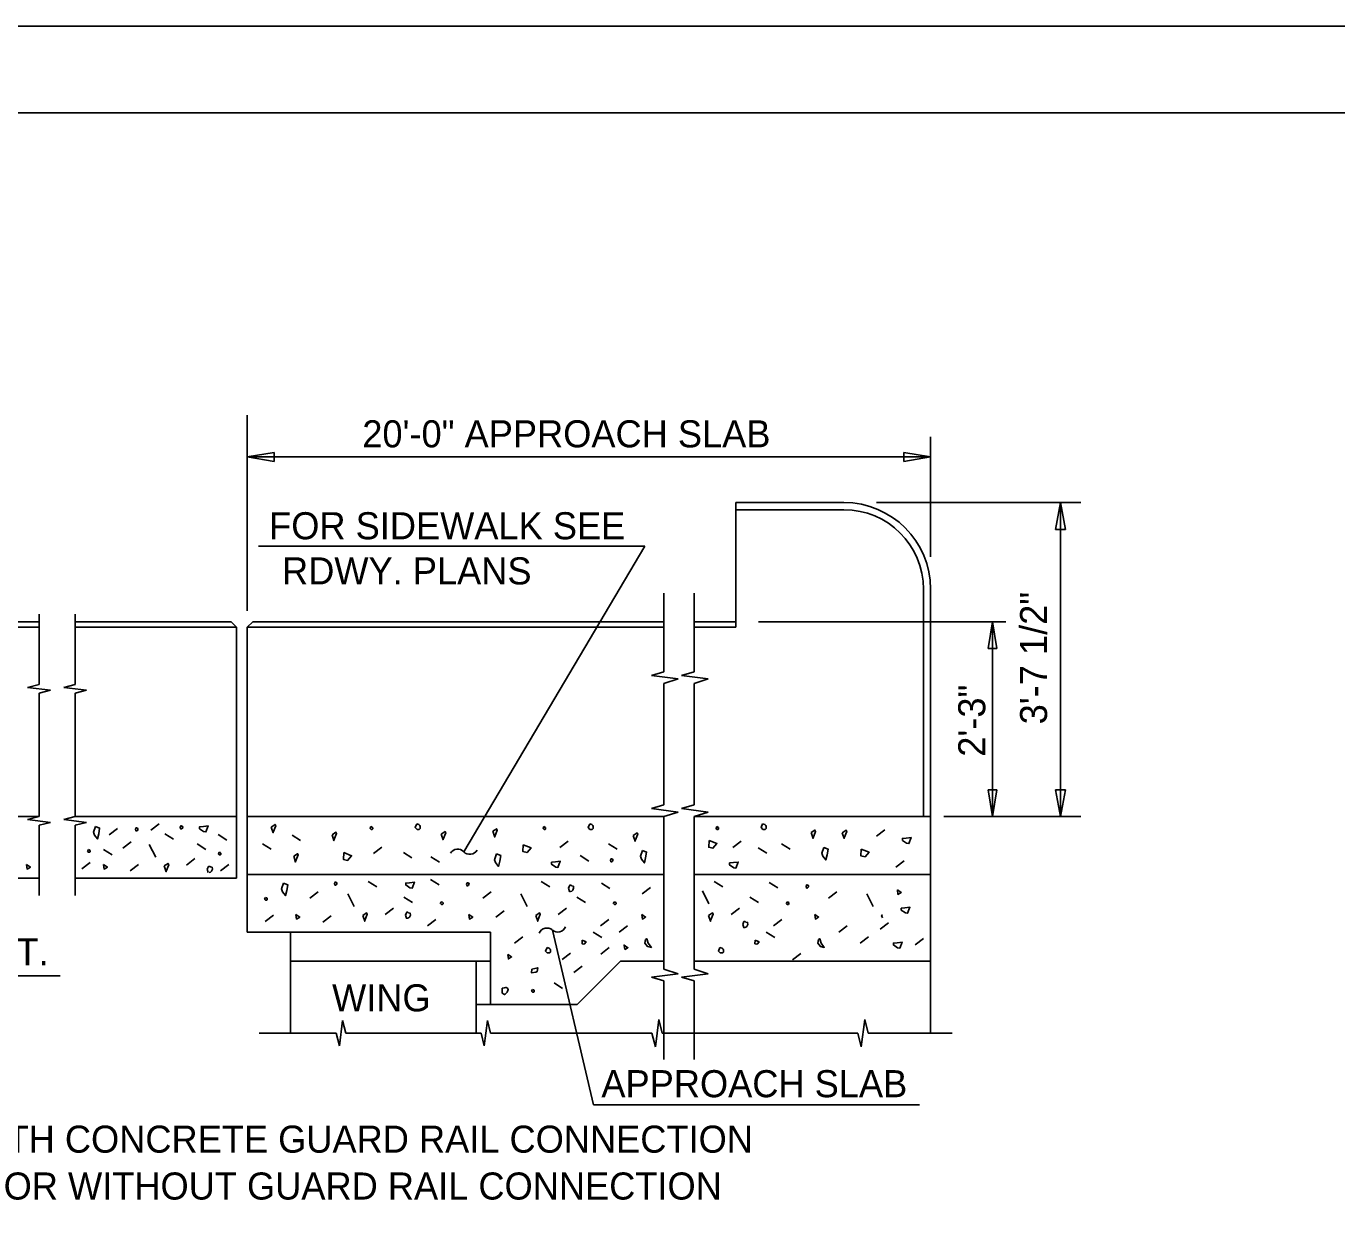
# Model space of a CAD drawing. Extents: x 0 to 68, y 0 to 47.1.
# Drawn here: x 27.27 to 42.4, y 30.18 to 44 of the extents above; entities that cross this region are included whole.
import ezdxf

# ---------------------------------------------------------------- set-up
doc = ezdxf.new("R2010")
doc.units = 0
for name, color, linetype in [('BORDER_ANNO_Cutsheet', 7, 'Continuous'), ('BRDG_ANNO_Anno-Sheet', 7, 'Continuous'), ('BRDG_ANNO_General-Notes', 7, 'Continuous'), ('BRDG_BASE_Obj-Line', 7, 'Continuous'), ('BRDG_BASE_Pattern', 7, 'Continuous')]:
    doc.layers.add(name, color=color, linetype=linetype)

msp = doc.modelspace()

# ---------------------------------------------------------------- linework, layer by layer
at = {"layer": 'BORDER_ANNO_Cutsheet'}
msp.add_lwpolyline([(0, 44), (68, 44), (68, 0), (0, 0)], close=True, dxfattribs=at)
at = {"layer": 'BRDG_ANNO_Anno-Sheet'}
msp.add_lwpolyline([(3, 43), (67, 43), (67, 1), (3, 1)], close=True, dxfattribs=at)
at = {"layer": 'BRDG_ANNO_General-Notes'}
for p, q in [((29.826, 39.512), (29.826, 37.253)), ((37.712, 39.262), (37.712, 37.891)), ((29.826, 39.028), (30.136, 39.08)), ((29.826, 39.028), (37.712, 39.028)), ((30.136, 38.976), (29.826, 39.028)), ((30.136, 39.08), (30.136, 38.976)), ((37.402, 38.976), (37.402, 39.08)), ((37.402, 39.08), (37.712, 39.028)), ((37.712, 39.028), (37.402, 38.976)), ((37.088, 38.502), (39.445, 38.502)), ((39.152, 38.192), (39.211, 38.502)), ((39.211, 34.877), (39.211, 38.502)), ((39.211, 38.502), (39.269, 38.192)), ((37.712, 38.401), (37.712, 37.876)), ((39.269, 38.192), (39.152, 38.192)), ((29.956, 38), (34.412, 38)), ((34.412, 38), (32.324, 34.471)), ((35.727, 37.127), (38.58, 37.127)), ((38.374, 36.817), (38.425, 37.127)), ((38.425, 37.127), (38.425, 34.877)), ((38.425, 37.127), (38.477, 36.817)), ((38.477, 36.817), (38.374, 36.817)), ((38.374, 35.187), (38.477, 35.187)), ((38.425, 34.877), (38.374, 35.187)), ((38.477, 35.187), (38.425, 34.877)), ((39.152, 35.187), (39.269, 35.187)), ((39.211, 34.877), (39.152, 35.187)), ((39.269, 35.187), (39.211, 34.877)), ((37.865, 34.877), (39.445, 34.877)), ((33.822, 31.552), (33.347, 33.568)), ((27.666, 33.041), (25.024, 33.041)), ((37.584, 31.552), (33.822, 31.552))]:
    msp.add_line(p, q, dxfattribs=at)
for centre, start, end in [((32.254, 34.405), 43.6688, 149.929), ((32.394, 34.538), 223.6688, 329.929), ((33.284, 33.494), 50.1499, 156.4101), ((33.409, 33.642), 230.1499, 336.4101)]:
    msp.add_arc(centre, 0.0969, start, end, dxfattribs=at)
at = {"layer": 'BRDG_BASE_Obj-Line'}
for p, q in [((36.712, 38.502), (35.462, 38.502)), ((35.462, 38.502), (35.462, 37.065)), ((36.712, 38.419), (35.462, 38.419)), ((34.634, 37.455), (34.634, 36.547)), ((34.982, 37.455), (34.982, 36.547)), ((37.629, 37.065), (37.629, 37.502)), ((37.712, 37.065), (37.712, 37.502)), ((27.423, 36.402), (27.423, 37.215)), ((27.839, 36.402), (27.839, 37.215)), ((25.906, 37.127), (27.423, 37.127)), ((25.99, 37.065), (27.423, 37.065)), ((29.638, 37.127), (27.839, 37.127)), ((27.839, 37.065), (29.701, 37.065)), ((29.638, 37.127), (29.701, 37.065)), ((29.701, 37.065), (29.701, 34.168)), ((29.826, 37.065), (29.888, 37.127)), ((29.826, 37.065), (29.826, 33.543)), ((34.634, 37.065), (29.826, 37.065)), ((34.634, 37.127), (29.888, 37.127)), ((35.462, 37.127), (34.982, 37.127)), ((35.462, 37.065), (34.982, 37.065)), ((37.629, 37.065), (37.629, 34.877)), ((37.712, 37.065), (37.712, 34.877)), ((34.489, 36.506), (34.634, 36.547)), ((34.797, 36.466), (34.489, 36.506)), ((34.634, 36.413), (34.797, 36.466)), ((34.837, 36.506), (34.982, 36.547)), ((35.144, 36.466), (34.837, 36.506)), ((34.982, 36.413), (35.144, 36.466)), ((27.423, 36.402), (27.29, 36.369)), ((27.29, 36.369), (27.555, 36.336)), ((27.555, 36.336), (27.423, 36.303)), ((27.423, 34.877), (27.423, 36.303)), ((27.839, 36.402), (27.707, 36.369)), ((27.707, 36.369), (27.972, 36.336)), ((27.972, 36.336), (27.839, 36.303)), ((27.839, 34.877), (27.839, 36.303)), ((34.634, 36.413), (34.634, 35.012)), ((34.982, 36.413), (34.982, 35.012)), ((34.489, 34.971), (34.634, 35.012)), ((34.797, 34.93), (34.489, 34.971)), ((34.837, 34.971), (34.982, 35.012)), ((35.144, 34.93), (34.837, 34.971)), ((23.572, 34.877), (27.423, 34.877)), ((27.423, 34.877), (27.29, 34.844)), ((27.29, 34.844), (27.555, 34.81)), ((27.555, 34.81), (27.423, 34.777)), ((27.839, 34.877), (27.707, 34.844)), ((27.707, 34.844), (27.972, 34.81)), ((29.701, 34.877), (27.839, 34.877)), ((27.972, 34.81), (27.839, 34.777)), ((34.634, 34.877), (29.826, 34.877)), ((34.634, 34.877), (34.797, 34.93)), ((34.634, 34.877), (34.634, 33.855)), ((34.982, 34.877), (35.144, 34.93)), ((34.982, 34.877), (34.982, 33.855)), ((37.712, 34.877), (34.982, 34.877)), ((37.712, 34.877), (37.712, 32.377)), ((27.423, 33.965), (27.423, 34.777)), ((27.839, 33.965), (27.839, 34.777)), ((34.634, 34.21), (29.826, 34.21)), ((37.712, 34.21), (34.982, 34.21)), ((23.572, 34.168), (27.423, 34.168)), ((29.701, 34.168), (27.839, 34.168)), ((34.634, 33.855), (34.634, 33.115)), ((34.982, 33.855), (34.982, 33.115)), ((29.826, 33.543), (32.634, 33.543)), ((30.326, 33.543), (30.326, 32.377)), ((32.634, 32.71), (32.634, 33.543)), ((30.326, 33.21), (31.775, 33.21)), ((31.349, 33.21), (32.467, 33.21)), ((32.467, 32.377), (32.467, 33.21)), ((34.134, 33.21), (33.634, 32.71)), ((34.134, 33.21), (34.634, 33.21)), ((34.982, 33.21), (37.712, 33.21)), ((34.797, 33.062), (34.489, 33.022)), ((34.489, 33.022), (34.634, 32.981)), ((34.634, 33.115), (34.797, 33.062)), ((34.634, 32.981), (34.634, 32.073)), ((35.144, 33.062), (34.837, 33.022)), ((34.837, 33.022), (34.982, 32.981)), ((34.982, 33.115), (35.144, 33.062)), ((34.982, 32.981), (34.982, 32.073)), ((32.634, 32.71), (33.634, 32.71)), ((30.889, 32.231), (30.926, 32.522)), ((30.926, 32.522), (30.962, 32.377)), ((32.561, 32.231), (32.597, 32.522)), ((32.597, 32.522), (32.634, 32.377)), ((34.535, 32.218), (34.575, 32.535)), ((34.575, 32.535), (34.614, 32.377)), ((36.912, 32.218), (36.951, 32.535)), ((36.951, 32.535), (36.991, 32.377)), ((30.853, 32.377), (29.963, 32.377)), ((30.853, 32.377), (30.889, 32.231)), ((32.525, 32.377), (30.962, 32.377)), ((32.525, 32.377), (32.561, 32.231)), ((33.524, 32.377), (32.634, 32.377)), ((34.495, 32.377), (33.524, 32.377)), ((34.495, 32.377), (34.535, 32.218)), ((36.872, 32.377), (34.614, 32.377)), ((36.872, 32.377), (36.912, 32.218)), ((37.962, 32.377), (36.991, 32.377))]:
    msp.add_line(p, q, dxfattribs=at)
for radius in [1, 0.917]:
    msp.add_arc((36.712, 37.502), radius, 0, 90, dxfattribs=at)
at = {"layer": 'BRDG_BASE_Pattern'}
for p, q in [((28.807, 34.795), (28.711, 34.722)), ((28.329, 34.74), (28.233, 34.667)), ((28.876, 34.68), (28.975, 34.618)), ((29.49, 34.67), (29.589, 34.607)), ((30.342, 34.664), (30.441, 34.601)), ((37.182, 34.723), (37.086, 34.65)), ((28.167, 34.498), (28.266, 34.436)), ((28.487, 34.587), (28.39, 34.514)), ((28.695, 34.557), (28.769, 34.41)), ((29.249, 34.562), (29.348, 34.499)), ((30.002, 34.564), (30.101, 34.501)), ((31.378, 34.523), (31.281, 34.45)), ((33.53, 34.593), (33.434, 34.52)), ((33.994, 34.564), (34.093, 34.501)), ((35.526, 34.593), (35.43, 34.52)), ((35.721, 34.518), (35.821, 34.455)), ((35.99, 34.564), (36.089, 34.501)), ((28.011, 34.347), (27.915, 34.273)), ((29.222, 34.392), (29.126, 34.318)), ((31.627, 34.464), (31.726, 34.402)), ((31.945, 34.414), (32.044, 34.352)), ((33.668, 34.427), (33.767, 34.364)), ((37.406, 34.366), (37.309, 34.293)), ((28.572, 34.326), (28.475, 34.253)), ((29.613, 34.326), (29.517, 34.253)), ((31.221, 34.127), (31.32, 34.065)), ((31.941, 34.151), (32.04, 34.089)), ((33.217, 34.127), (33.316, 34.065)), ((33.912, 34.11), (34.011, 34.047)), ((34.478, 34.058), (34.382, 33.984)), ((35.213, 34.127), (35.312, 34.065)), ((35.85, 34.118), (35.949, 34.055)), ((30.643, 34.008), (30.547, 33.935)), ((30.987, 33.986), (31.06, 33.839)), ((31.634, 33.947), (31.733, 33.884)), ((32.639, 34.008), (32.543, 33.935)), ((32.982, 33.986), (33.056, 33.839)), ((33.63, 33.947), (33.729, 33.884)), ((35.078, 34.019), (35.151, 33.872)), ((35.626, 33.947), (35.725, 33.884)), ((36.631, 34.008), (36.535, 33.935)), ((36.974, 33.986), (37.048, 33.839)), ((30.13, 33.74), (30.033, 33.667)), ((30.793, 33.732), (30.697, 33.659)), ((31.513, 33.82), (31.417, 33.747)), ((32.789, 33.79), (32.693, 33.717)), ((33.509, 33.82), (33.413, 33.747)), ((35.505, 33.82), (35.409, 33.747)), ((32.002, 33.691), (31.905, 33.617)), ((33.998, 33.691), (33.901, 33.617)), ((34.215, 33.617), (34.119, 33.543)), ((35.994, 33.691), (35.897, 33.617)), ((36.748, 33.617), (36.652, 33.543)), ((37.227, 33.65), (37.131, 33.577)), ((33.005, 33.49), (32.908, 33.416)), ((33.818, 33.543), (33.917, 33.481)), ((35.814, 33.543), (35.913, 33.481)), ((36.996, 33.49), (36.9, 33.416)), ((37.629, 33.471), (37.533, 33.398)), ((33.555, 33.299), (33.458, 33.226)), ((34.003, 33.365), (33.907, 33.291)), ((36.214, 33.298), (36.118, 33.225)), ((33.692, 33.149), (33.596, 33.076)), ((33.366, 32.957), (33.465, 32.894))]:
    msp.add_line(p, q, dxfattribs=at)
for points in [[(31.781, 34.792), (31.763, 34.751), (31.785, 34.729), (31.811, 34.729), (31.822, 34.741), (31.822, 34.762), (31.818, 34.773), (31.807, 34.785)], [(33.777, 34.792), (33.759, 34.751), (33.78, 34.729), (33.807, 34.729), (33.818, 34.741), (33.818, 34.762), (33.814, 34.773), (33.803, 34.785)], [(35.773, 34.792), (35.755, 34.751), (35.776, 34.729), (35.803, 34.729), (35.814, 34.741), (35.814, 34.762), (35.81, 34.773), (35.799, 34.785)], [(28.074, 34.763), (28.051, 34.697), (28.063, 34.664), (28.096, 34.62), (28.111, 34.679), (28.122, 34.745)], [(28.534, 34.729), (28.54, 34.711), (28.545, 34.711), (28.553, 34.713), (28.558, 34.718), (28.563, 34.729), (28.562, 34.74), (28.553, 34.742), (28.549, 34.746), (28.541, 34.746)], [(29.051, 34.753), (29.056, 34.734), (29.062, 34.734), (29.069, 34.736), (29.075, 34.741), (29.08, 34.753), (29.078, 34.764), (29.069, 34.765), (29.065, 34.769), (29.058, 34.769)], [(29.319, 34.763), (29.274, 34.759), (29.274, 34.737), (29.322, 34.704), (29.348, 34.701), (29.374, 34.771)], [(30.103, 34.757), (30.125, 34.691), (30.125, 34.698), (30.155, 34.772), (30.147, 34.787)], [(30.804, 34.666), (30.826, 34.6), (30.826, 34.607), (30.856, 34.681), (30.848, 34.696)], [(31.252, 34.761), (31.243, 34.74), (31.254, 34.729), (31.267, 34.729), (31.273, 34.735), (31.273, 34.746), (31.271, 34.751), (31.265, 34.757)], [(32.064, 34.676), (32.086, 34.609), (32.086, 34.616), (32.116, 34.69), (32.108, 34.705)], [(32.659, 34.708), (32.682, 34.641), (32.682, 34.648), (32.711, 34.722), (32.704, 34.737)], [(33.248, 34.761), (33.239, 34.74), (33.25, 34.729), (33.263, 34.729), (33.269, 34.735), (33.269, 34.746), (33.267, 34.751), (33.261, 34.757)], [(34.279, 34.659), (34.302, 34.593), (34.302, 34.6), (34.331, 34.674), (34.324, 34.688)], [(35.244, 34.761), (35.235, 34.74), (35.246, 34.729), (35.259, 34.729), (35.265, 34.735), (35.265, 34.746), (35.263, 34.751), (35.257, 34.757)], [(36.333, 34.692), (36.355, 34.626), (36.355, 34.633), (36.385, 34.707), (36.377, 34.721)], [(36.692, 34.691), (36.715, 34.625), (36.715, 34.632), (36.744, 34.706), (36.737, 34.721)], [(37.431, 34.629), (37.387, 34.625), (37.387, 34.603), (37.435, 34.57), (37.461, 34.566), (37.487, 34.636)], [(27.992, 34.496), (27.982, 34.476), (27.993, 34.465), (28.007, 34.465), (28.012, 34.471), (28.012, 34.482), (28.01, 34.487), (28.004, 34.493)], [(33.01, 34.553), (33.006, 34.474), (33.054, 34.462), (33.1, 34.516)], [(34.386, 34.487), (34.363, 34.42), (34.375, 34.387), (34.408, 34.343), (34.422, 34.402), (34.434, 34.468)], [(35.155, 34.602), (35.151, 34.523), (35.199, 34.512), (35.245, 34.566)], [(36.48, 34.522), (36.458, 34.456), (36.469, 34.422), (36.502, 34.378), (36.517, 34.437), (36.528, 34.503)], [(36.911, 34.503), (36.907, 34.424), (36.955, 34.413), (37.001, 34.466)], [(28.867, 34.307), (28.89, 34.241), (28.89, 34.248), (28.92, 34.322), (28.912, 34.337)], [(29.502, 34.466), (29.492, 34.445), (29.503, 34.434), (29.516, 34.434), (29.522, 34.44), (29.522, 34.451), (29.52, 34.456), (29.514, 34.462)], [(30.361, 34.419), (30.384, 34.353), (30.384, 34.36), (30.414, 34.434), (30.406, 34.449)], [(30.94, 34.462), (30.936, 34.383), (30.984, 34.372), (31.03, 34.425)], [(32.702, 34.446), (32.679, 34.379), (32.691, 34.346), (32.724, 34.302), (32.739, 34.361), (32.75, 34.427)], [(33.381, 34.354), (33.337, 34.35), (33.337, 34.328), (33.385, 34.295), (33.411, 34.291), (33.437, 34.361)], [(34.017, 34.374), (34.023, 34.356), (34.028, 34.356), (34.036, 34.358), (34.041, 34.363), (34.046, 34.374), (34.045, 34.385), (34.036, 34.387), (34.032, 34.391), (34.024, 34.391)], [(35.435, 34.346), (35.391, 34.342), (35.391, 34.32), (35.439, 34.287), (35.465, 34.283), (35.491, 34.353)], [(27.277, 34.323), (27.285, 34.272), (27.322, 34.294)], [(28.167, 34.323), (28.174, 34.272), (28.211, 34.294)], [(30.244, 34.108), (30.222, 34.042), (30.233, 34.009), (30.266, 33.965), (30.281, 34.024), (30.292, 34.09)], [(30.831, 34.105), (30.837, 34.086), (30.842, 34.086), (30.85, 34.088), (30.855, 34.094), (30.861, 34.105), (30.859, 34.116), (30.85, 34.118), (30.846, 34.122), (30.839, 34.122)], [(31.699, 34.114), (31.655, 34.11), (31.655, 34.088), (31.703, 34.055), (31.729, 34.052), (31.755, 34.121)], [(32.356, 34.097), (32.362, 34.078), (32.367, 34.078), (32.375, 34.08), (32.38, 34.085), (32.386, 34.097), (32.384, 34.108), (32.375, 34.11), (32.371, 34.113), (32.364, 34.113)], [(33.533, 34.051), (33.544, 34.014), (33.555, 34.014), (33.57, 34.018), (33.581, 34.028), (33.592, 34.051), (33.589, 34.073), (33.57, 34.077), (33.562, 34.084), (33.548, 34.084)], [(36.274, 34.072), (36.28, 34.053), (36.285, 34.053), (36.292, 34.055), (36.298, 34.061), (36.303, 34.072), (36.302, 34.083), (36.292, 34.085), (36.288, 34.089), (36.281, 34.089)], [(30.036, 33.944), (30.026, 33.924), (30.037, 33.913), (30.05, 33.913), (30.056, 33.919), (30.056, 33.929), (30.054, 33.935), (30.048, 33.941)], [(32.065, 33.895), (32.055, 33.874), (32.066, 33.863), (32.079, 33.863), (32.085, 33.869), (32.085, 33.88), (32.083, 33.885), (32.077, 33.891)], [(34.061, 33.895), (34.051, 33.874), (34.062, 33.863), (34.075, 33.863), (34.081, 33.869), (34.081, 33.88), (34.079, 33.885), (34.073, 33.891)], [(36.056, 33.895), (36.047, 33.874), (36.058, 33.863), (36.071, 33.863), (36.077, 33.869), (36.077, 33.88), (36.075, 33.885), (36.069, 33.891)], [(37.328, 34.03), (37.335, 33.979), (37.372, 34.001)], [(30.386, 33.747), (30.394, 33.695), (30.431, 33.718)], [(31.159, 33.736), (31.181, 33.67), (31.181, 33.677), (31.211, 33.751), (31.203, 33.766)], [(31.651, 33.74), (31.663, 33.703), (31.673, 33.703), (31.688, 33.707), (31.699, 33.718), (31.71, 33.74), (31.707, 33.762), (31.688, 33.766), (31.68, 33.774), (31.666, 33.774)], [(32.382, 33.747), (32.39, 33.695), (32.427, 33.718)], [(33.154, 33.736), (33.177, 33.67), (33.177, 33.677), (33.207, 33.751), (33.199, 33.766)], [(34.378, 33.747), (34.386, 33.695), (34.423, 33.718)], [(35.15, 33.736), (35.173, 33.67), (35.173, 33.677), (35.203, 33.751), (35.195, 33.766)], [(36.374, 33.747), (36.382, 33.695), (36.419, 33.718)], [(37.416, 33.824), (37.372, 33.82), (37.372, 33.798), (37.42, 33.765), (37.446, 33.761), (37.472, 33.831)], [(35.544, 33.633), (35.555, 33.596), (35.566, 33.596), (35.581, 33.6), (35.592, 33.61), (35.602, 33.633), (35.599, 33.655), (35.581, 33.659), (35.573, 33.666), (35.558, 33.666)], [(33.691, 33.449), (33.689, 33.409), (33.713, 33.404), (33.736, 33.43)], [(34.423, 33.46), (34.415, 33.418), (34.443, 33.378), (34.489, 33.368), (34.452, 33.417), (34.436, 33.468)], [(35.687, 33.449), (35.685, 33.409), (35.709, 33.404), (35.732, 33.43)], [(36.419, 33.46), (36.411, 33.418), (36.439, 33.378), (36.485, 33.368), (36.448, 33.417), (36.432, 33.468)], [(37.327, 33.421), (37.283, 33.418), (37.283, 33.396), (37.331, 33.363), (37.357, 33.359), (37.382, 33.429)], [(32.831, 33.286), (32.839, 33.235), (32.876, 33.257)], [(33.285, 33.365), (33.267, 33.325), (33.288, 33.303), (33.315, 33.303), (33.326, 33.314), (33.326, 33.336), (33.322, 33.347), (33.311, 33.358)], [(35.281, 33.365), (35.263, 33.325), (35.284, 33.303), (35.311, 33.303), (35.322, 33.314), (35.322, 33.336), (35.318, 33.347), (35.307, 33.358)], [(32.634, 33.21), (32.467, 33.21), (32.467, 32.71), (32.634, 32.71)], [(33.111, 33.118), (33.104, 33.074), (33.156, 33.082), (33.17, 33.089), (33.178, 33.133)], [(32.769, 32.896), (32.769, 32.84), (32.794, 32.822), (32.802, 32.829), (32.823, 32.851), (32.838, 32.881), (32.828, 32.896), (32.813, 32.903), (32.806, 32.903), (32.791, 32.899)], [(33.116, 32.883), (33.107, 32.862), (33.118, 32.851), (33.131, 32.851), (33.136, 32.857), (33.136, 32.868), (33.135, 32.873), (33.129, 32.879)]]:
    msp.add_lwpolyline(points, close=True, dxfattribs=at)
for points in [[(29.386, 34.233), (29.401, 34.237), (29.412, 34.248), (29.423, 34.27), (29.42, 34.292), (29.401, 34.296), (29.394, 34.303), (29.379, 34.303), (29.364, 34.27)], [(29.364, 34.27), (29.376, 34.233)], [(37.156, 33.743), (37.146, 33.736), (37.156, 33.708)], [(34.182, 33.342), (34.219, 33.364), (34.175, 33.394), (34.182, 33.342)]]:
    msp.add_lwpolyline(points, dxfattribs=at)

# ---------------------------------------------------------------- texts
at = {"layer": 'BRDG_ANNO_General-Notes'}
for s, p in [('20\'-0" APPROACH SLAB', (31.153, 39.139)), ('FOR SIDEWALK SEE  ', (30.078, 38.078)), ('RDWY. PLANS', (30.227, 37.557)), ('CONST. JT.', (25.258, 33.16)), ('WING', (30.804, 32.629)), ('APPROACH SLAB', (33.912, 31.638)), ('WITH CONCRETE GUARD RAIL CONNECTION', (26.537, 30.998)), ('OR WITHOUT GUARD RAIL CONNECTION', (27.014, 30.457))]:
    msp.add_text(s, height=0.3125, dxfattribs=at).set_placement(p)
for s, p in [('3\'-7 1/2"', (39.056, 35.942)), ('2\'-3"', (38.343, 35.568))]:
    msp.add_text(s, height=0.3125, rotation=90, dxfattribs=at).set_placement(p)

doc.saveas('drawing.dxf')
